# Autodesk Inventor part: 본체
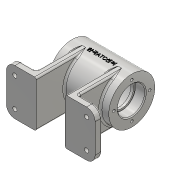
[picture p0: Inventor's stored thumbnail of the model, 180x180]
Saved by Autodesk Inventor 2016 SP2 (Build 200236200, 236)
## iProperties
Created: 2017-02
Part Number: 본체
Material: 알루미늄 6061
Document SubType Name: Modeling
Designer: H
Density: 2.7 g/cm^3
Appearance: 알루미늄 - 평지
Mass: 354.768 g
Surface Area: 422.768 cm^2
Volume: 131.396 cm^3
Author: H
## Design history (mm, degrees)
sketch "스케치1"
  geometry: L1 (0, 25.622)-(0, -36.506); L2 (52, 27)-(17, 27); L3 (17, 27)-(17, -27); L4 (17, -27)-(52, -27); L5 (52, -27)-(52, 27); L6 (0, 0)-(60.827, 0); L7 (-52, 27)-(-17, 27); L8 (-52, -27)-(-52, 27); L9 (-17, 27)-(-17, -27); L10 (-17, -27)-(-52, -27)
  constraints: 20 end point, 4 symmetric about line, 2 horizontal, 2 parallel, 1 perpendicular, 1 point on line, 1 vertical, 1 other
  dimensions: "d0" = 52 distance between parallel lines of L1 L5; "d1" = 17 distance between parallel lines of L1 L3; "d2" = 54 distance of L4.end L2.start
extrude "돌출1" new body sketch "스케치1" distance "d3" = 8; taper "d4" = 0 deg
sketch "스케치2"
  geometry: L1 (0, 27)-(0, -27) reference; C1 r 27 at (60, 0); 1 further point
  constraints: 1 centre point
  dimensions: "d5" = 54 diameter of C1; "d6" = 60 distance from line of L1 C1.centre
extrude "돌출2" join sketch "스케치2" stored distance "d7" = 70; taper "d8" = 0 deg
sketch "스케치3"
  geometry: L1 (-17, 0)-(-17, 8) reference; L2 (17, 0)-(17, 8) reference; L3 (17, 8)-(17, 60); L4 (17, 60)-(25, 60); L5 (25, 60)-(25, 8); L6 (25, 8)-(17, 8); L7 (-35, 87)-(35, 87) reference; L8 (0, 0)-(0, 87); L9 (-25, 8)-(-17, 8); L10 (-25, 60)-(-25, 8); L11 (-17, 8)-(-17, 60); L12 (-17, 60)-(-25, 60); L13 (35, 33)-(35, 87) reference; L14 (-35, 87)-(-35, 33) reference; L15 (35, 60)-(-35, 60); L16 (-17, 0)-(-52, 0) reference; L17 (-15, 92)-(-10, 92); L18 (-10, 92)-(-10, 72.116); L19 (-10, 72.116)-(-15, 72.116); L20 (-15, 72.116)-(-15, 92)
  constraints: 28 end point, 3 midpoint, 3 parallel, 3 perpendicular, 3 symmetric about line, 1 horizontal, 1 point on line, 1 vertical
  dimensions: "d9" = 8 distance of L3.end L4.end; "d13" = 92 distance between parallel lines of L16 L17; "d14" = 5 distance of L17.start L17.end; "d16" = 25 distance between parallel lines of L14 L18; "d17" = 19.88427 distance between parallel lines of L19 L17
extrude "돌출3" join sketch "스케치3" stored distance "d11" = 54; taper "d12" = 0 deg
revolve "회전1" stored, may be unused: angle "d18" = 90 deg
sketch "스케치4"
  geometry: C1 r 27 at (0, 0) reference; C2 r 16 at (0, 0); 1 further point
  constraints: 1 centre point, 1 coincident
  dimensions: "d19" = 32 diameter of C2
extrude "돌출4" cut sketch "스케치4" distance "d20" = 12; taper "d21" = 0 deg
sketch "스케치5"
  geometry: C1 r 16 at (0, 0) reference; C2 r 14 at (0, 0); 1 further point
  constraints: 1 centre point, 1 coincident
  dimensions: "d22" = 28 diameter of C2
extrude "돌출5" cut sketch "스케치5" distance "d23" = 3; taper "d24" = 0 deg
sketch "스케치6"
  geometry: C1 r 14 at (0, 0) reference; C2 r 22 at (0, 0); 1 further point
  constraints: 1 centre point, 1 coincident
  dimensions: "d25" = 44 diameter of C2
extrude "돌출6" cut sketch "스케치6" distance "d26" = 40; taper "d27" = 0 deg
sketch "스케치7"
  geometry: C1 r 27 at (0, 0) reference; C2 r 14 at (0, 0); 1 further point
  constraints: 1 centre point, 1 coincident
  dimensions: "d28" = 28 diameter of C2
extrude "돌출7" cut sketch "스케치7" distance "d29" = 3; taper "d30" = 0 deg
sketch "스케치8"
  geometry: C1 r 14 at (0, 0) reference; C2 r 16 at (0, 0); 1 further point
  constraints: 1 centre point, 1 coincident
  dimensions: "d31" = 32 diameter of C2
extrude "돌출8" cut sketch "스케치8" distance "d32" = 12; taper "d33" = 0 deg
chamfer "모따기1" distance "d34" = 1; stored, may be unused: second distance "d35" = 2, angle "d36" = 45 deg
chamfer "모따기2" distance "d37" = 1; stored, may be unused: second distance "d38" = 2, angle "d39" = 45 deg
fillet "모깎기1" dims "d40" = 3
fillet "모깎기2" dims "d41" = 0.3
sketch "스케치9" dims "d42" = 42
  geometry: L1 (0, 0)-(0, 21); C1 r 27 at (0, 0) reference; 2 further points
  constraints: 2 coincident, 2 end point, 1 vertical, 1 vertical alignment, 2 other
hole "구멍1" sketch "스케치9" at (0, 21) diameter "d43" = 3.242; stored, may be unused: countersink angle "d47" = 90 deg, drill point angle "d49" = 118 deg; dims "d44" = 8, "d45" = 4, "d46" = 2, "d48" = 10
node "작업 평면1"
fillet "모깎기3" dims "d53" = 10
sketch "스케치10" dims "d92" = 9
  geometry: L1 (42, 17)-(42, 21.5); L2 (44.598, 21.5)-(47.196, 17); L3 (47.196, 17)-(44.598, 12.5); L4 (44.598, 12.5)-(39.402, 12.5); L5 (39.402, 12.5)-(36.804, 17); L6 (36.804, 17)-(39.402, 21.5); L7 (39.402, 21.5)-(44.598, 21.5); C1 r 2.5 at (42, 17); A1 r 10 centre (42, 17) between (52, 17) and (42, 27) reference; 3 further points
  constraints: 14 end point, 4 coincident, 1 centre point, 1 midpoint, 1 vertical, 1 vertical alignment, 15 other
  dimensions: "d57" = 5 diameter of C1
extrude "돌출9" cut sketch "스케치10" distance "d55" = 3; taper "d56" = 0 deg
extrude "돌출10" cut sketch "스케치10" stored distance "d58" = 3; taper "d59" = 0 deg
sketch "스케치11"
  geometry: C1 r 5 at (0, 0) reference; 2 further points
  constraints: 1 coincident
hole "구멍2" sketch "스케치11" at (0, 0) diameter "d66" = 5.188; stored, may be unused: countersink angle "d70" = 90 deg, drill point angle "d72" = 118 deg; dims "d67" = 12, "d68" = 4, "d69" = 2, "d71" = 25
fillet "모깎기4" dims "d73" = 2
fillet "모깎기5" dims "d74" = 2
fillet "모깎기6" dims "d75" = 2
fillet "모깎기7" dims "d76" = 2
node "작업 평면2"
sketch "스케치12"
  geometry: L1 (-35, 87)-(35, 87) reference; L2 (35, 33)-(35, 87) reference; L3 (-35, 87)-(-35, 33) reference; L4 (-35, 33)-(35, 33) reference; L5 (-35, 60)-(35, 60); L6 (0, 87)-(0, 33); 3 further points
  constraints: 5 midpoint, 4 end point, 1 coincident, 1 other
feature "엠보싱1" sketch "스케치12" dims "d78" = 0.5, "d79" = 0
sketch "스케치13"
  geometry: L1 (60, 0)-(33, 0); L2 (60, 0)-(34.84, -16.339); L3 (34.84, -16.339)-(31.572, -11.307); L4 (31.572, -11.307)-(37.622, -7.378); L5 (37.622, -7.378)-(40.89, -12.41); 1 further point
  constraints: 10 end point, 2 perpendicular, 1 horizontal, 1 horizontal alignment, 1 point on line, 1 other
  dimensions: "d80" = 33 deg angle of L1 L2; "d81" = 30 distance of L1.start L2.end; "d82" = 12 diameter of L4 L2; "d93" = 7.21351 distance of L3.end L4.end
revolve "회전2" sketch "스케치13" stored, may be unused: angle "d83" = 90 deg
sketch "스케치14"
  geometry: C1 r 6 at (0, 0) reference; 2 further points
  constraints: 1 coincident
hole "구멍3" sketch "스케치14" at (0, 0) diameter "d84" = 5.188; stored, may be unused: countersink angle "d88" = 90 deg, drill point angle "d90" = 118 deg; dims "d85" = 20, "d86" = 4, "d87" = 2, "d89" = 24
fillet "모깎기8" dims "d91" = 2
node "솔리드1"
pattern_circular "원형 패턴1" dims angle "d51" = 360 deg
mirror "대칭1"
pattern_linear "직사각형 패턴1" dims "d62" = 84, "d65" = 34
node "투영된 루프1"
